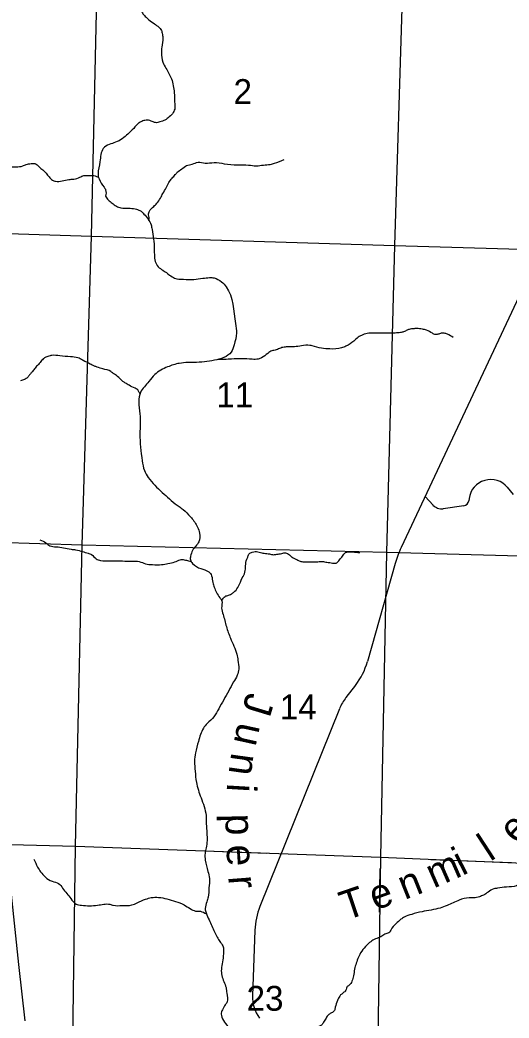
# Model space of a CAD drawing. Extents: x 1219626 to 1426462, y 456797 to 752399.
# Drawn here: x 1329747 to 1338132, y 576968 to 594067 of the extents above; entities that cross this region are included whole.
import ezdxf

# ---------------------------------------------------------------- set-up
doc = ezdxf.new("R2010")
doc.units = 0
for name, color, linetype in [('Masks', 7, 'Continuous'), ('Narrow River Creek and Branch and Slough', 7, 'Continuous'), ('Narrow River Creek and Branch and Slough Text', 7, 'Continuous'), ('Section Lines', 7, 'Continuous'), ('Section Numbers', 7, 'Continuous'), ('State Route Divided Highway Outline and Fill', 7, 'Continuous'), ('Uninventoried Roads and Features', 7, 'Continuous')]:
    doc.layers.add(name, color=color, linetype=linetype)

msp = doc.modelspace()

# ---------------------------------------------------------------- linework, layer by layer
at = {"layer": 'Masks'}
for p, q in [((1333073, 579825), (1333973, 579792)), ((1336791, 579686), (1338174, 579631)), ((1335913, 578783), (1335923, 579527))]:
    msp.add_line(p, q, dxfattribs=at)
at = {"layer": 'Narrow River Creek and Branch and Slough'}
for points in [[(1332188, 599594), (1332081, 599563), (1331963, 599511), (1331929, 599493), (1331887, 599455), (1331863, 599431), (1331742, 599372), (1331645, 599338), (1331465, 599241), (1331351, 599175), (1331282, 599134), (1331123, 598995), (1331047, 598929), (1330905, 598829), (1330808, 598743), (1330715, 598660), (1330663, 598604), (1330545, 598393), (1330442, 598175), (1330456, 598099), (1330511, 597867), (1330518, 597784), (1330511, 597604), (1330532, 597521), (1330577, 597341), (1330587, 597143), (1330601, 596943), (1330587, 596870), (1330559, 596735), (1330494, 596576), (1330462, 596521), (1330411, 596451), (1330390, 596386), (1330383, 596185), (1330376, 596036), (1330359, 595867), (1330359, 595759), (1330393, 595657), (1330535, 595588), (1330722, 595505), (1330836, 595460), (1330971, 595367), (1331030, 595294), (1331102, 595180), (1331144, 595014), (1331178, 594907), (1331275, 594716), (1331313, 594633), (1331403, 594486), (1331472, 594410), (1331579, 594344), (1331673, 594309), (1331790, 594275), (1331828, 594219), (1331866, 594161), (1331925, 594098), (1332032, 594015), (1332109, 593960), (1332164, 593904), (1332185, 593839), (1332198, 593763), (1332178, 593602), (1332171, 593506), (1332198, 593343), (1332250, 593239), (1332344, 593056), (1332375, 592941), (1332392, 592820), (1332399, 592661), (1332403, 592561), (1332375, 592481), (1332306, 592405), (1332233, 592353), (1332147, 592319), (1332071, 592308), (1331994, 592336), (1331908, 592350), (1331835, 592329), (1331780, 592298), (1331697, 592210), (1331597, 592113), (1331500, 592033), (1331386, 591971), (1331275, 591933), (1331175, 591864), (1331119, 591639), (1331085, 591431), (1331102, 591345), (1331189, 591203), (1331216, 591154), (1331216, 591047)], [(1331959, 590631), (1331960, 590680), (1331953, 590728), (1331967, 590794), (1332040, 590874), (1332095, 590926), (1332154, 591016), (1332199, 591095), (1332254, 591192), (1332299, 591282), (1332355, 591358), (1332410, 591417), (1332444, 591458), (1332521, 591514), (1332604, 591573), (1332700, 591597), (1332801, 591628), (1332922, 591614), (1333074, 591625), (1333250, 591604), (1333472, 591586), (1333665, 591580), (1333797, 591569), (1333921, 591580), (1334039, 591593), (1334111, 591611), (1334277, 591676)], [(1329007, 591538), (1329169, 591545), (1329404, 591552), (1329681, 591552), (1329795, 591566), (1329854, 591593), (1329937, 591607), (1330002, 591607), (1330075, 591552), (1330196, 591441), (1330245, 591379), (1330307, 591320), (1330355, 591303), (1330583, 591334), (1330670, 591341), (1330774, 591372), (1330843, 591400), (1330936, 591400), (1331012, 591400), (1331057, 591386), (1331090, 591376)], [(1331216, 591047), (1331261, 590984), (1331327, 590929), (1331400, 590877), (1331479, 590849), (1331604, 590842), (1331721, 590829), (1331804, 590801), (1331873, 590742), (1331943, 590656), (1331994, 590559), (1332012, 590479), (1332050, 590150), (1332067, 589929), (1332115, 589839), (1332198, 589780), (1332313, 589697), (1332399, 589645), (1332548, 589624), (1332728, 589621), (1332880, 589642), (1332997, 589652), (1333074, 589648), (1333202, 589582), (1333282, 589496), (1333441, 588866), (1333461, 588703), (1333417, 588502), (1333368, 588374), (1333244, 588284), (1333123, 588246), (1332953, 588215), (1332773, 588201), (1332479, 588184), (1332279, 588123), (1332058, 587991), (1331959, 587875), (1331814, 587685), (1331783, 587529), (1331804, 587318), (1331804, 586979), (1331842, 586515), (1331880, 586349), (1331945, 586231), (1332187, 585972), (1332308, 585864), (1332443, 585754), (1332513, 585705), (1332637, 585591), (1332685, 585539), (1332789, 585380), (1332827, 585273), (1332813, 585127), (1332706, 584979), (1332672, 584878), (1332668, 584819), (1332706, 584757), (1332848, 584667), (1332983, 584612), (1333031, 584546), (1333052, 584428), (1333076, 584349), (1333172, 584168), (1333207, 584116), (1333203, 583992), (1333228, 583884), (1333286, 583673), (1333356, 583473), (1333463, 583199), (1333484, 583099), (1333497, 582947), (1333473, 582839), (1333408, 582725), (1333325, 582573), (1333155, 582265), (1333072, 582130), (1332958, 582015), (1332892, 581932), (1332806, 581707), (1332757, 581510), (1332740, 581368), (1332750, 581195), (1332771, 581005), (1332851, 580742), (1332937, 580437), (1332941, 580295), (1332951, 580133), (1332941, 579884), (1332920, 579790), (1332923, 579672), (1332968, 579479)], [(1337175, 588627), (1337074, 588683), (1337022, 588700), (1336984, 588703), (1336926, 588686), (1336870, 588676), (1336818, 588700), (1336718, 588752), (1336645, 588769), (1336552, 588780), (1336486, 588776), (1336434, 588769), (1336383, 588752), (1336324, 588724), (1336268, 588710), (1336182, 588703), (1335833, 588703), (1335726, 588700), (1335625, 588672), (1335546, 588631), (1335470, 588565), (1335335, 588478), (1335259, 588447), (1335062, 588430), (1334916, 588444), (1334757, 588482), (1334719, 588492), (1334574, 588482), (1334332, 588465), (1334256, 588458), (1334180, 588430), (1334138, 588413), (1334064, 588399), (1333995, 588354), (1333887, 588278), (1333832, 588257), (1333728, 588254), (1333372, 588257), (1333255, 588250), (1333144, 588251)], [(1331805, 587665), (1331800, 587673), (1331787, 587697), (1331776, 587721), (1331721, 587756), (1331617, 587808), (1331555, 587846), (1331510, 587874), (1331420, 587960), (1331347, 588012), (1331306, 588043), (1331168, 588088), (1331071, 588119), (1331022, 588137), (1330953, 588171), (1330829, 588234), (1330780, 588261), (1330739, 588279), (1330614, 588296), (1330431, 588313), (1330296, 588320), (1330262, 588313), (1330192, 588289), (1330147, 588261), (1330092, 588199), (1330033, 588133), (1330006, 588102), (1329961, 588047), (1329926, 588002), (1329895, 587967), (1329853, 587922), (1329822, 587905), (1329757, 587884)], [(1330089, 585161), (1330193, 585109), (1330260, 585058), (1330369, 585042), (1330494, 585026), (1330624, 585000), (1330701, 584990), (1330821, 584959), (1330914, 584933), (1330976, 584907), (1331054, 584834), (1331127, 584808), (1331298, 584803), (1331505, 584798), (1331661, 584793), (1331791, 584788), (1331900, 584751), (1332019, 584736), (1332175, 584736), (1332284, 584757), (1332403, 584782), (1332491, 584819), (1332564, 584819), (1332636, 584798), (1332681, 584787)], [(1333208, 584114), (1333236, 584165), (1333262, 584191), (1333324, 584212), (1333386, 584243), (1333433, 584279), (1333495, 584367), (1333558, 584507), (1333604, 584606), (1333615, 584715), (1333635, 584829), (1333656, 584876), (1333677, 584923), (1333729, 584949), (1333781, 584959), (1333869, 584943), (1333957, 584928), (1334004, 584923), (1334076, 584907), (1334149, 584912), (1334237, 584928), (1334299, 584938), (1334331, 584928), (1334403, 584871), (1334455, 584840), (1334533, 584803), (1334595, 584783), (1334683, 584783), (1334829, 584783), (1334927, 584788), (1335010, 584777), (1335104, 584762), (1335166, 584762), (1335212, 584798), (1335264, 584866), (1335290, 584897), (1335311, 584928), (1335353, 584949), (1335430, 584954), (1335503, 584949), (1335570, 584938)], [(1339006, 584312), (1338984, 584169), (1338990, 584033), (1338990, 583985), (1338977, 583944), (1338949, 583871), (1338923, 583753), (1338895, 583576), (1338847, 583382), (1338816, 583249), (1338809, 583128), (1338809, 583027), (1338838, 582884), (1338869, 582808), (1338971, 582646), (1339037, 582570), (1339088, 582465), (1339114, 582278), (1339129, 582106), (1339136, 581979), (1339129, 581897), (1339072, 581751), (1339037, 581662), (1338999, 581459), (1338961, 581259), (1338942, 581148), (1338923, 580894), (1338911, 580609), (1338895, 580558), (1338835, 580374), (1338803, 580234), (1338793, 580142), (1338736, 579997), (1338692, 579882), (1338638, 579781), (1338587, 579705), (1338527, 579540), (1338473, 579438), (1338435, 579378), (1338394, 579318), (1338337, 579283), (1338257, 579233), (1338089, 579211), (1337934, 579191), (1337870, 579182), (1337772, 579125), (1337696, 579074), (1337626, 579046), (1337525, 579027), (1337446, 579027), (1337278, 578988), (1337068, 578893), (1336951, 578852), (1336640, 578789), (1336463, 578744), (1336336, 578697), (1336279, 578659), (1336196, 578586), (1336104, 578475), (1336085, 578440), (1336022, 578411), (1335952, 578370), (1335914, 578351), (1335819, 578313), (1335742, 578259), (1335647, 578167), (1335571, 578056), (1335549, 578011), (1335511, 577907), (1335482, 577805), (1335467, 577691), (1335438, 577599), (1335387, 577526), (1335352, 577497), (1335340, 577456), (1335302, 577409), (1335229, 577345), (1335191, 577266), (1335153, 577152), (1335137, 577098), (1335089, 577056), (1335042, 577028), (1334994, 576968), (1334953, 576895), (1334915, 576847), (1334823, 576809), (1334687, 576790), (1334563, 576749), (1334363, 576676), (1334255, 576679), (1334173, 576695)], [(1329987, 579689), (1330049, 579554), (1330101, 579471), (1330184, 579383), (1330298, 579310), (1330407, 579274), (1330479, 579191), (1330619, 579014), (1330708, 578921), (1330801, 578900), (1331076, 578900), (1331289, 578916), (1331346, 578900), (1331501, 578895), (1331667, 578905), (1331756, 578942), (1331901, 579004), (1331999, 579030), (1332124, 579035), (1332264, 579009), (1332560, 578905), (1332663, 578843), (1332757, 578801), (1332840, 578796), (1332944, 578752)], [(1332968, 579479), (1332996, 579358), (1332986, 579198), (1332975, 579039), (1332951, 578960), (1332923, 578842), (1332937, 578769), (1332989, 578648), (1333082, 578444), (1333127, 578354), (1333172, 578278), (1333224, 578205), (1333235, 578066), (1333221, 577928), (1333200, 577804), (1333207, 577696), (1333280, 577489), (1333293, 577392), (1333297, 577243), (1333266, 577195), (1333217, 577108), (1333197, 577035), (1333207, 576983), (1333352, 576771), (1333397, 576709), (1333439, 576657), (1333452, 576543), (1333421, 576443), (1333418, 576353), (1333376, 576280), (1333311, 576235), (1333262, 576166), (1333262, 576007), (1333276, 575823), (1333288, 575788)]]:
    msp.add_spline(points, degree=3, dxfattribs=at)
at = {"layer": 'Section Lines'}
for p, q in [((1330971, 590364), (1331094, 595662)), ((1336334, 595544), (1336170, 590204)), ((1325752, 590520), (1330971, 590364)), ((1330814, 585068), (1330971, 590364)), ((1330971, 590364), (1336170, 590204)), ((1336170, 590204), (1336032, 584943)), ((1336170, 590204), (1341391, 590049)), ((1330814, 585068), (1325573, 585231)), ((1330699, 579912), (1330814, 585068)), ((1336032, 584943), (1330814, 585068)), ((1336032, 584943), (1335925, 579721)), ((1341292, 584795), (1336032, 584943)), ((1325372, 580050), (1330699, 579912)), ((1330628, 574600), (1330699, 579912)), ((1330699, 579912), (1335925, 579721)), ((1335925, 579721), (1335855, 574490)), ((1335925, 579721), (1341183, 579510))]:
    msp.add_line(p, q, dxfattribs=at)
at = {"layer": 'State Route Divided Highway Outline and Fill'}
msp.add_lwpolyline([(1329836, 576922), (1329726, 577886), (1329603, 579083), (1329471, 580281), (1329440, 580562), (1329341, 581487), (1329211, 582681), (1329081, 583890), (1328949, 585093), (1328817, 586294), (1328782, 586623), (1328737, 586979), (1328682, 587299), (1328641, 587505), (1328602, 587690), (1328532, 587994), (1328442, 588336), (1328327, 588729), (1327991, 589918), (1327621, 591179), (1327307, 592324), (1326961, 593553), (1326616, 594750)], dxfattribs=at)
at = {"layer": 'Uninventoried Roads and Features'}
for p, q in [((1338788, 590371), (1336282, 585029)), ((1338207, 585938), (1338105, 586060)), ((1336828, 585757), (1336693, 585904)), ((1337446, 585869), (1337441, 585829)), ((1337356, 585743), (1337003, 585694)), ((1336180, 584755), (1335703, 583074)), ((1335499, 582668), (1335336, 582458)), ((1335227, 582267), (1333862, 578876)), ((1333776, 578473), (1333733, 577350))]:
    msp.add_line(p, q, dxfattribs=at)
for centre, radius, start, end in [((1337818, 585819), 375, 39.945, 172.3648), ((1337342, 585842), 100, 278.0468, 352.3648), ((1336975, 585892), 200, 222.4511, 278.0468), ((1337912, 584265), 1800, 154.8655, 164.1824), ((1334549, 583401), 1200, 322.3228, 344.1824), ((1335969, 581969), 800, 142.3228, 158.0645), ((1334975, 578428), 1200, 158.0645, 177.8494), ((1334333, 577328), 600, 177.8494, 216.9177)]:
    msp.add_arc(centre, radius, start, end, dxfattribs=at)

# ---------------------------------------------------------------- texts
at = {"layer": 'Narrow River Creek and Branch and Slough Text'}
for s, rotation, p in [('J', 253.2071, (1333644, 582564)), ('u', 257.6017, (1333489, 582051)), ('n', 262.1122, (1333373, 581528)), ('i', 266.6859, (1333299, 580997)), ('p', 271.2654, (1333267, 580463)), ('e', 46.9393, (1338266, 579929)), ('l', 33.1423, (1337809, 579642)), ('e', 273.6895, (1333282, 579927)), ('i', 27.2864, (1337331, 579400)), ('m', 23.7312, (1336840, 579185)), ('r', 274.4534, (1333317, 579393)), ('n', 21.554, (1336342, 578989)), ('T', 18.6996, (1335331, 578635)), ('e', 19.936, (1335838, 578807))]:
    msp.add_text(s, height=500, rotation=rotation, dxfattribs=at).set_placement(p)
at = {"layer": 'Section Numbers'}
for s, rotation, p in [('2', 0.0001, (1333408, 592628)), ('11', 0.0001, (1333113, 587431)), ('14', 0.0002, (1334201, 582086)), ('23', 0.0002, (1333632, 577093))]:
    msp.add_text(s, height=425, rotation=rotation, dxfattribs=at).set_placement(p)

doc.saveas('drawing.dxf')
